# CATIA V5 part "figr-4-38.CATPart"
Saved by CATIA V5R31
Part number: Part1
Bounding box of the stored display mesh (mm): x 0 to 127.525, y -106.271 to 100, z 0 to 100
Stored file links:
  D:\PROJECTS\Project 2021\US EDITION\CATIA V5 6R 2021\Resources\Part Files\c04_catia_v5_6r2020_prt\figr-4-38.CATPart
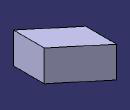
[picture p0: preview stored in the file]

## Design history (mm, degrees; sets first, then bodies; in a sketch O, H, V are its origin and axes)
Body1 (main body)
  Sketch1 on yz-plane, origin (0, 0, 0), H (0, 1, 0), V (0, 0, 1)
    line L1 (0, 0) -> (100, 0)
    line L2 (100, 0) -> (100, 100)
    line L3 (100, 100) -> (0, 100)
    line L4 (0, 100) -> (0, 0)
    horizontal: L1 H, L3 H
    vertical: L2 V, L4 V
  Sketch2 on xy-plane, origin (0, 0, 0), H (1, 0, 0), V (0, 1, 0)
    line L1 (0, 0) -> (60, -50)
  Pad1: profile Sketch1, direction along edge of Sketch2, length 166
